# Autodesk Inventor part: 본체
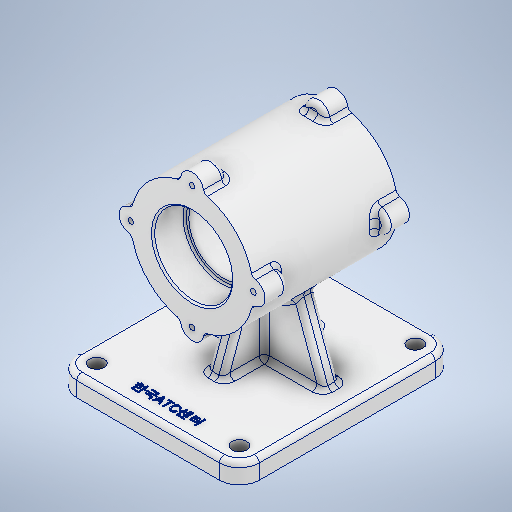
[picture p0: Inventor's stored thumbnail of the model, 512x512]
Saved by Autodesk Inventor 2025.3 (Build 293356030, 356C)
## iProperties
Created: 2025-08
Part Number: 본체
Material: 알루미늄 6061
Document SubType Name: Modeling
Designer: user
Density: 2.7 g/cm^3
Appearance: 알루미늄 - 평지
Mass: 1222.68 g
Surface Area: 800.379 cm^2
Volume: 452.843 cm^3
Author: user
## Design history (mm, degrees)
sketch "스케치2"
  geometry: L1 (43, 65)-(-43, 65); L2 (-55, 53)-(-55, -53); L3 (-43, -65)-(43, -65); L4 (55, -53)-(55, 53); L5 (55, 65)-(-55, -65); L6 (-55, 65)-(55, -65); A1 r 12 centre (43, 53) between (55, 53) and (43, 65); A2 r 12 centre (-43, 53) between (-43, 65) and (-55, 53); A3 r 12 centre (43, -53) between (43, -65) and (55, -53); A4 r 12 centre (-43, -53) between (-55, -53) and (-43, -65); 1 further point
  constraints: 12 end point, 8 point on circle, 8 point on line, 8 tangent, 4 centre point, 3 equal radius, 2 midpoint, 2 parallel, 1 horizontal, 1 perpendicular
  dimensions: "d0" = 130 distance between parallel lines of L3 L1; "d1" = 110 distance between parallel lines of L4 L2; "d2" = 12 radius of A1
extrude "돌출1" new body sketch "스케치2" distance "d3" = 12; taper "d4" = 0 deg
sketch "스케치3"
  geometry: L1 (-43, -53)-(43, -53); L2 (43, -53)-(43, 53); L3 (43, 53)-(-43, 53); L4 (-43, 53)-(-43, -53); L5 (-43, -53)-(43, 53); L6 (43, -53)-(-43, 53); 1 further point
  constraints: 12 end point, 2 midpoint, 2 parallel, 1 horizontal, 1 perpendicular
  dimensions: "d5" = 86 distance of L3.end L2.end; "d6" = 106 distance of L2.end L1.end
hole "구멍1" sketch "스케치3" at (43, -53), (-43, -53), (-43, 53), (43, 53) diameter "d7" = 9; stored, may be unused: countersink angle "d11" = 90 deg, drill point angle "d13" = 118 deg; dims "d8" = 6, "d9" = 4, "d10" = 2, "d12" = 8
sketch "스케치4"
  geometry: L1 (119, 38.5)-(82, 38.5); L2 (82, 38.5)-(82, -48.5); L3 (82, -48.5)-(119, -48.5); L4 (119, -48.5)-(119, 38.5); L5 (0, 53)-(0, -53) reference; L6 (0, 65)-(12, 65) reference; L7 (82, 38.5)-(105.5, 38.5); L8 (105.5, 38.5)-(105.5, 19.5); L9 (105.5, 19.5)-(82, 19.5); L10 (82, 19.5)-(82, 38.5); L11 (82, -48.5)-(105.5, -48.5); L12 (105.5, -48.5)-(105.5, -29.5); L13 (105.5, -29.5)-(82, -29.5); L14 (82, -29.5)-(82, -48.5); L15 (82, 19.5)-(103, 19.5); L16 (103, 19.5)-(103, -29.5); L17 (103, -29.5)-(82, -29.5); L18 (82, -29.5)-(82, 19.5); 6 further points
  constraints: 32 end point, 8 parallel, 4 horizontal, 4 perpendicular, 2 midpoint, 1 point on line
  dimensions: "d14" = 37 distance of L3.end L2.end; "d15" = 87 distance of L2.end L1.end; "d16" = 82 distance between parallel lines of L5 L2; "d17" = 70 vertical distance of point (6, 65) point (119, -5); "d18" = 23.5 distance of L8.end L9.end; "d19" = 19 distance of L7.end L8.end; "d20" = 23.5 distance of L13.end L12.end; "d21" = 19 distance of L12.end L11.end; "d22" = 21 distance of L16.end L17.end
revolve "회전1" sketch "스케치4" stored, may be unused: angle "d23" = 90 deg
sketch "스케치5"
  geometry: L1 (0, 0)-(0, 37); C1 r 7 at (0, 37); C2 r 7 at (-37, 0); C3 r 7 at (0, -37); C4 r 7 at (37, 0); 2 further points
  constraints: 4 centre point, 2 end point, 1 coincident, 1 vertical, 1 vertical alignment, 10 other
  dimensions: "d25" = 0 distance from line of point (0, 0) L1; "d26" = 0 distance of L1.start point (0, 0); "d31" = 14 diameter of C1; "d34" = 360 deg dimension on L1.start C1.centre (derived)
extrude "돌출2" join sketch "스케치5" distance "d36" = 14; taper "d37" = 0 deg
sketch "스케치7"
  geometry: A1 r 7 centre (0, 0) between (6.969, -0.662) and (-6.969, -0.662) reference; A2 r 7 centre (37, -37) between (36.338, -43.969) and (36.338, -30.031) reference; A3 r 7 centre (0, -74) between (-6.969, -73.338) and (6.969, -73.338) reference; A4 r 7 centre (-37, -37) between (-36.338, -30.031) and (-36.338, -43.969) reference; 1 further point
hole "구멍2" sketch "스케치7" at (-37, -37), (0, -74), (0, 0), (37, -37) diameter "d38" = 3.242; stored, may be unused: countersink angle "d42" = 90 deg, drill point angle "d44" = 118 deg; dims "d39" = 8, "d40" = 4, "d41" = 2, "d43" = 10
node "작업 평면1"
sketch "스케치8"
  geometry: L1 (-43, -65)-(43, -65) reference; L2 (0, -65)-(0, 5); L3 (0, -65)-(70, -65); L4 (-5, 0)-(5, 0); L5 (5, 0)-(5, 10); L6 (5, 10)-(-5, 10); L7 (-5, 10)-(-5, 0); L8 (-5, 0)-(5, 10); L9 (5, 0)-(-5, 10); 1 further point
  constraints: 16 end point, 3 midpoint, 2 horizontal, 2 parallel, 2 perpendicular, 1 vertical
  dimensions: "d46" = 70 distance of L2.start L2.end; "d47" = 90 deg angle of L3 L2 (derived); "d48" = 10 distance of L6.end L5.end; "d49" = 10 distance of L5.end L4.end
extrude "돌출3" join sketch "스케치8" stored distance "d50" = 0; taper "d51" = 0 deg
node "작업 평면2"
sketch "스케치12"
  geometry: L1 (55, 12)-(43, 12) reference; L2 (55, 12)-(41, 12); L3 (38.5, 12)-(47.5, 12) reference; L4 (41, 12)-(25.336, 55.036); A1 r 37 centre (0, 82) between (6.969, 45.662) and (36.338, 75.031) reference; 1 further point
  constraints: 4 end point, 1 point on circle, 1 point on line
  dimensions: "d60" = 14 distance of L1.start L2.end; "d61" = 110 deg angle of L4 L1
feature "리브1" sketch "스케치12" dims "d62" = 1, "d63" = 10, "d64" = 0, "d65" = 0, "d66" = 1, "d67" = 1
sketch "스케치14"
  geometry: L1 (45, 24.5)-(45, -34.5) reference; L2 (12, -65)-(12, -53) reference; L3 (12, -65)-(12, -35); L4 (12, 53)-(12, -53) reference; L5 (12, -35)-(45, -22.989); 2 further points
  constraints: 4 end point, 3 point on line
  dimensions: "d73" = 110 deg angle of L3 L5; "d74" = 30 distance of L2.start L3.end; "d94" = 60 distance of L3.end point (12, 25)
feature "리브2" sketch "스케치14" dims "d75" = 1, "d76" = 10, "d77" = 0, "d78" = 0, "d79" = 1, "d80" = 1
fillet "모깎기1" dims "d81" = 1
fillet "모깎기2" dims "d82" = 3
fillet "모깎기3" dims "d83" = 3
sketch "스케치15"
  geometry: L1 (-13.888, -49.998)-(13.888, -49.998); L2 (13.888, -49.998)-(13.888, -56.002); L3 (13.888, -56.002)-(-13.888, -56.002); L4 (-13.888, -56.002)-(-13.888, -49.998); L5 (77, 5)-(-77, 5) reference; L6 (6.889, -27.5)-(-6.889, -27.5) reference; 4 further points
  constraints: 3 midpoint, 2 other
  dimensions: "d84" = 58 distance from line of L5 point (13.888, -53); "d85" = 0 horizontal distance of point (0, -49.998) point (0, -27.5)
feature "엠보싱1" sketch "스케치15" dims "d0" = 130, "d1" = 110, "d2" = 12, "d7" = 9, "d86" = 0.5, "d87" = 0
chamfer "모따기1" distance "d88" = 1; stored, may be unused: second distance "d89" = 2, angle "d90" = 45 deg
chamfer "모따기2" distance "d91" = 1; stored, may be unused: second distance "d92" = 2, angle "d93" = 45 deg
node "솔리드1"
mirror "미러1"
mirror "미러2"
mirror "미러3"
node "스케치 - 원형 패턴2" dims "d34" = 360 deg (derived)
feature "A9D066F2-1C7D-4E18-AEED-F7BC21143FA4" dims "d7" = 9, "d8" = 6, "d9" = 4, "d10" = 2, "d11" = 90 deg, "d12" = 8, "d13" = 118 deg
other parameters: "d45" = -43.5, "d59" = -5
